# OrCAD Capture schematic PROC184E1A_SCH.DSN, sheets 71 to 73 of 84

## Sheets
71 30. SOC CORE HCPS-B: size C; title: HCPS B; note: PROC184_SCH
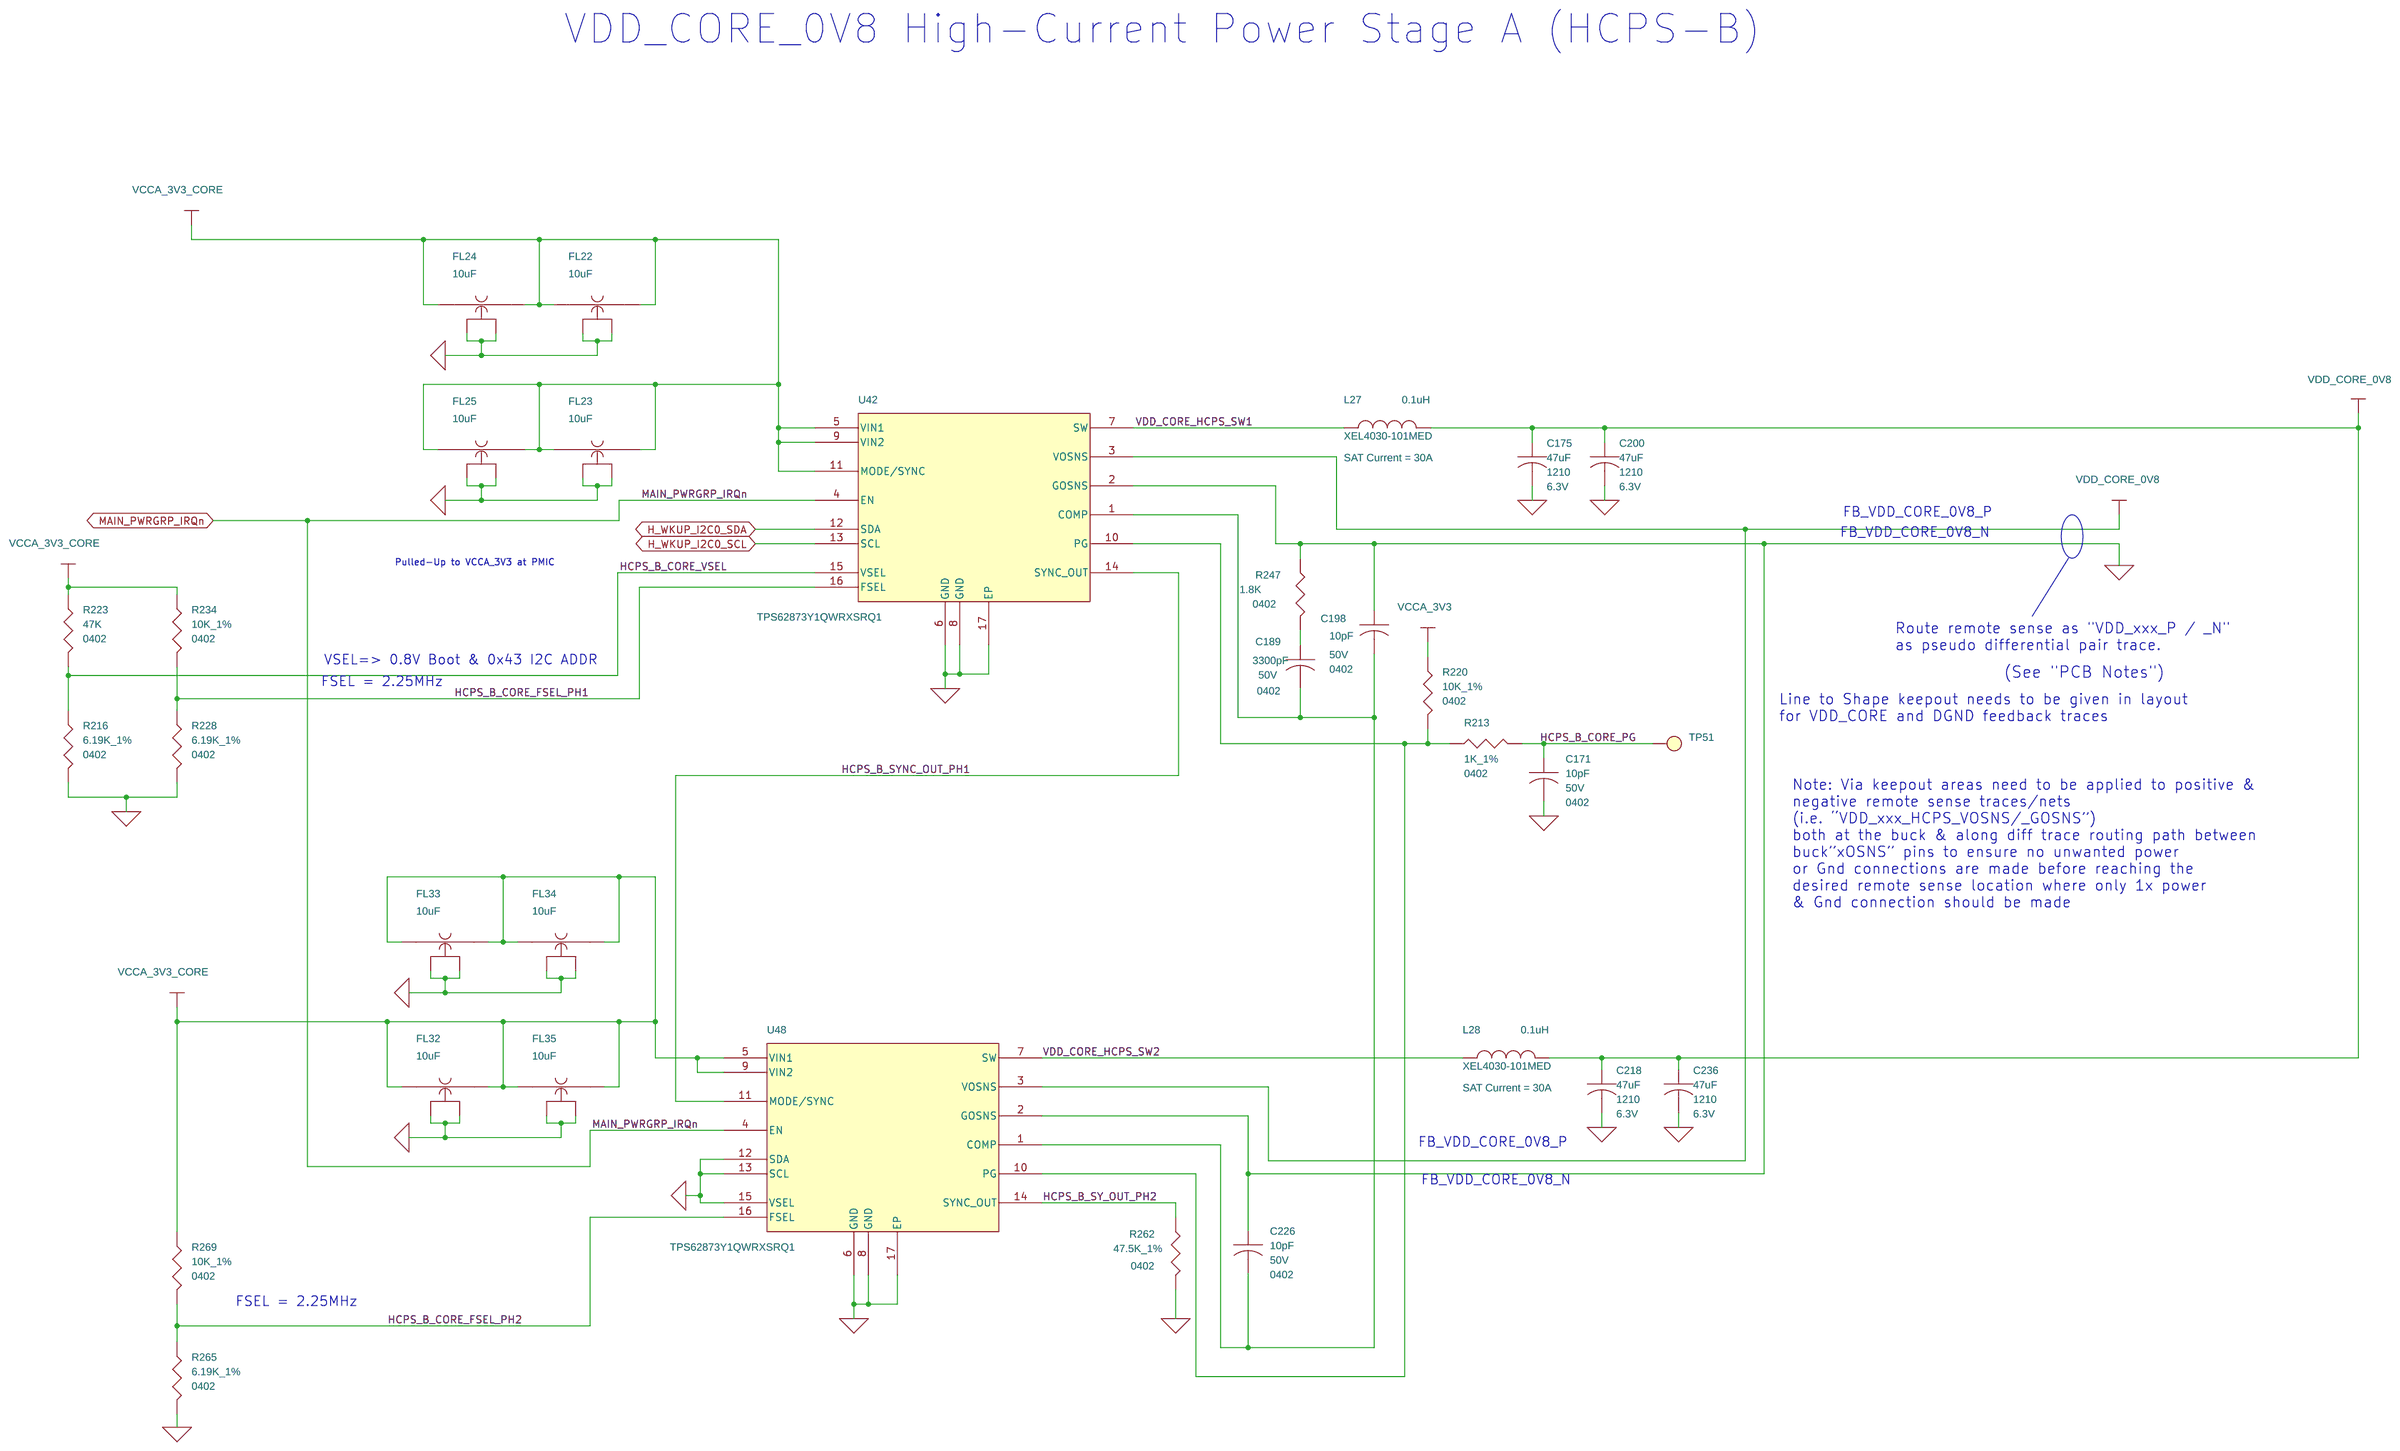
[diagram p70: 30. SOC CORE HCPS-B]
72 31. SOC LDOs & LD SWITCHES: size C; title: SOC LDO's and LD_SWITCHES; note: PROC184_SCH
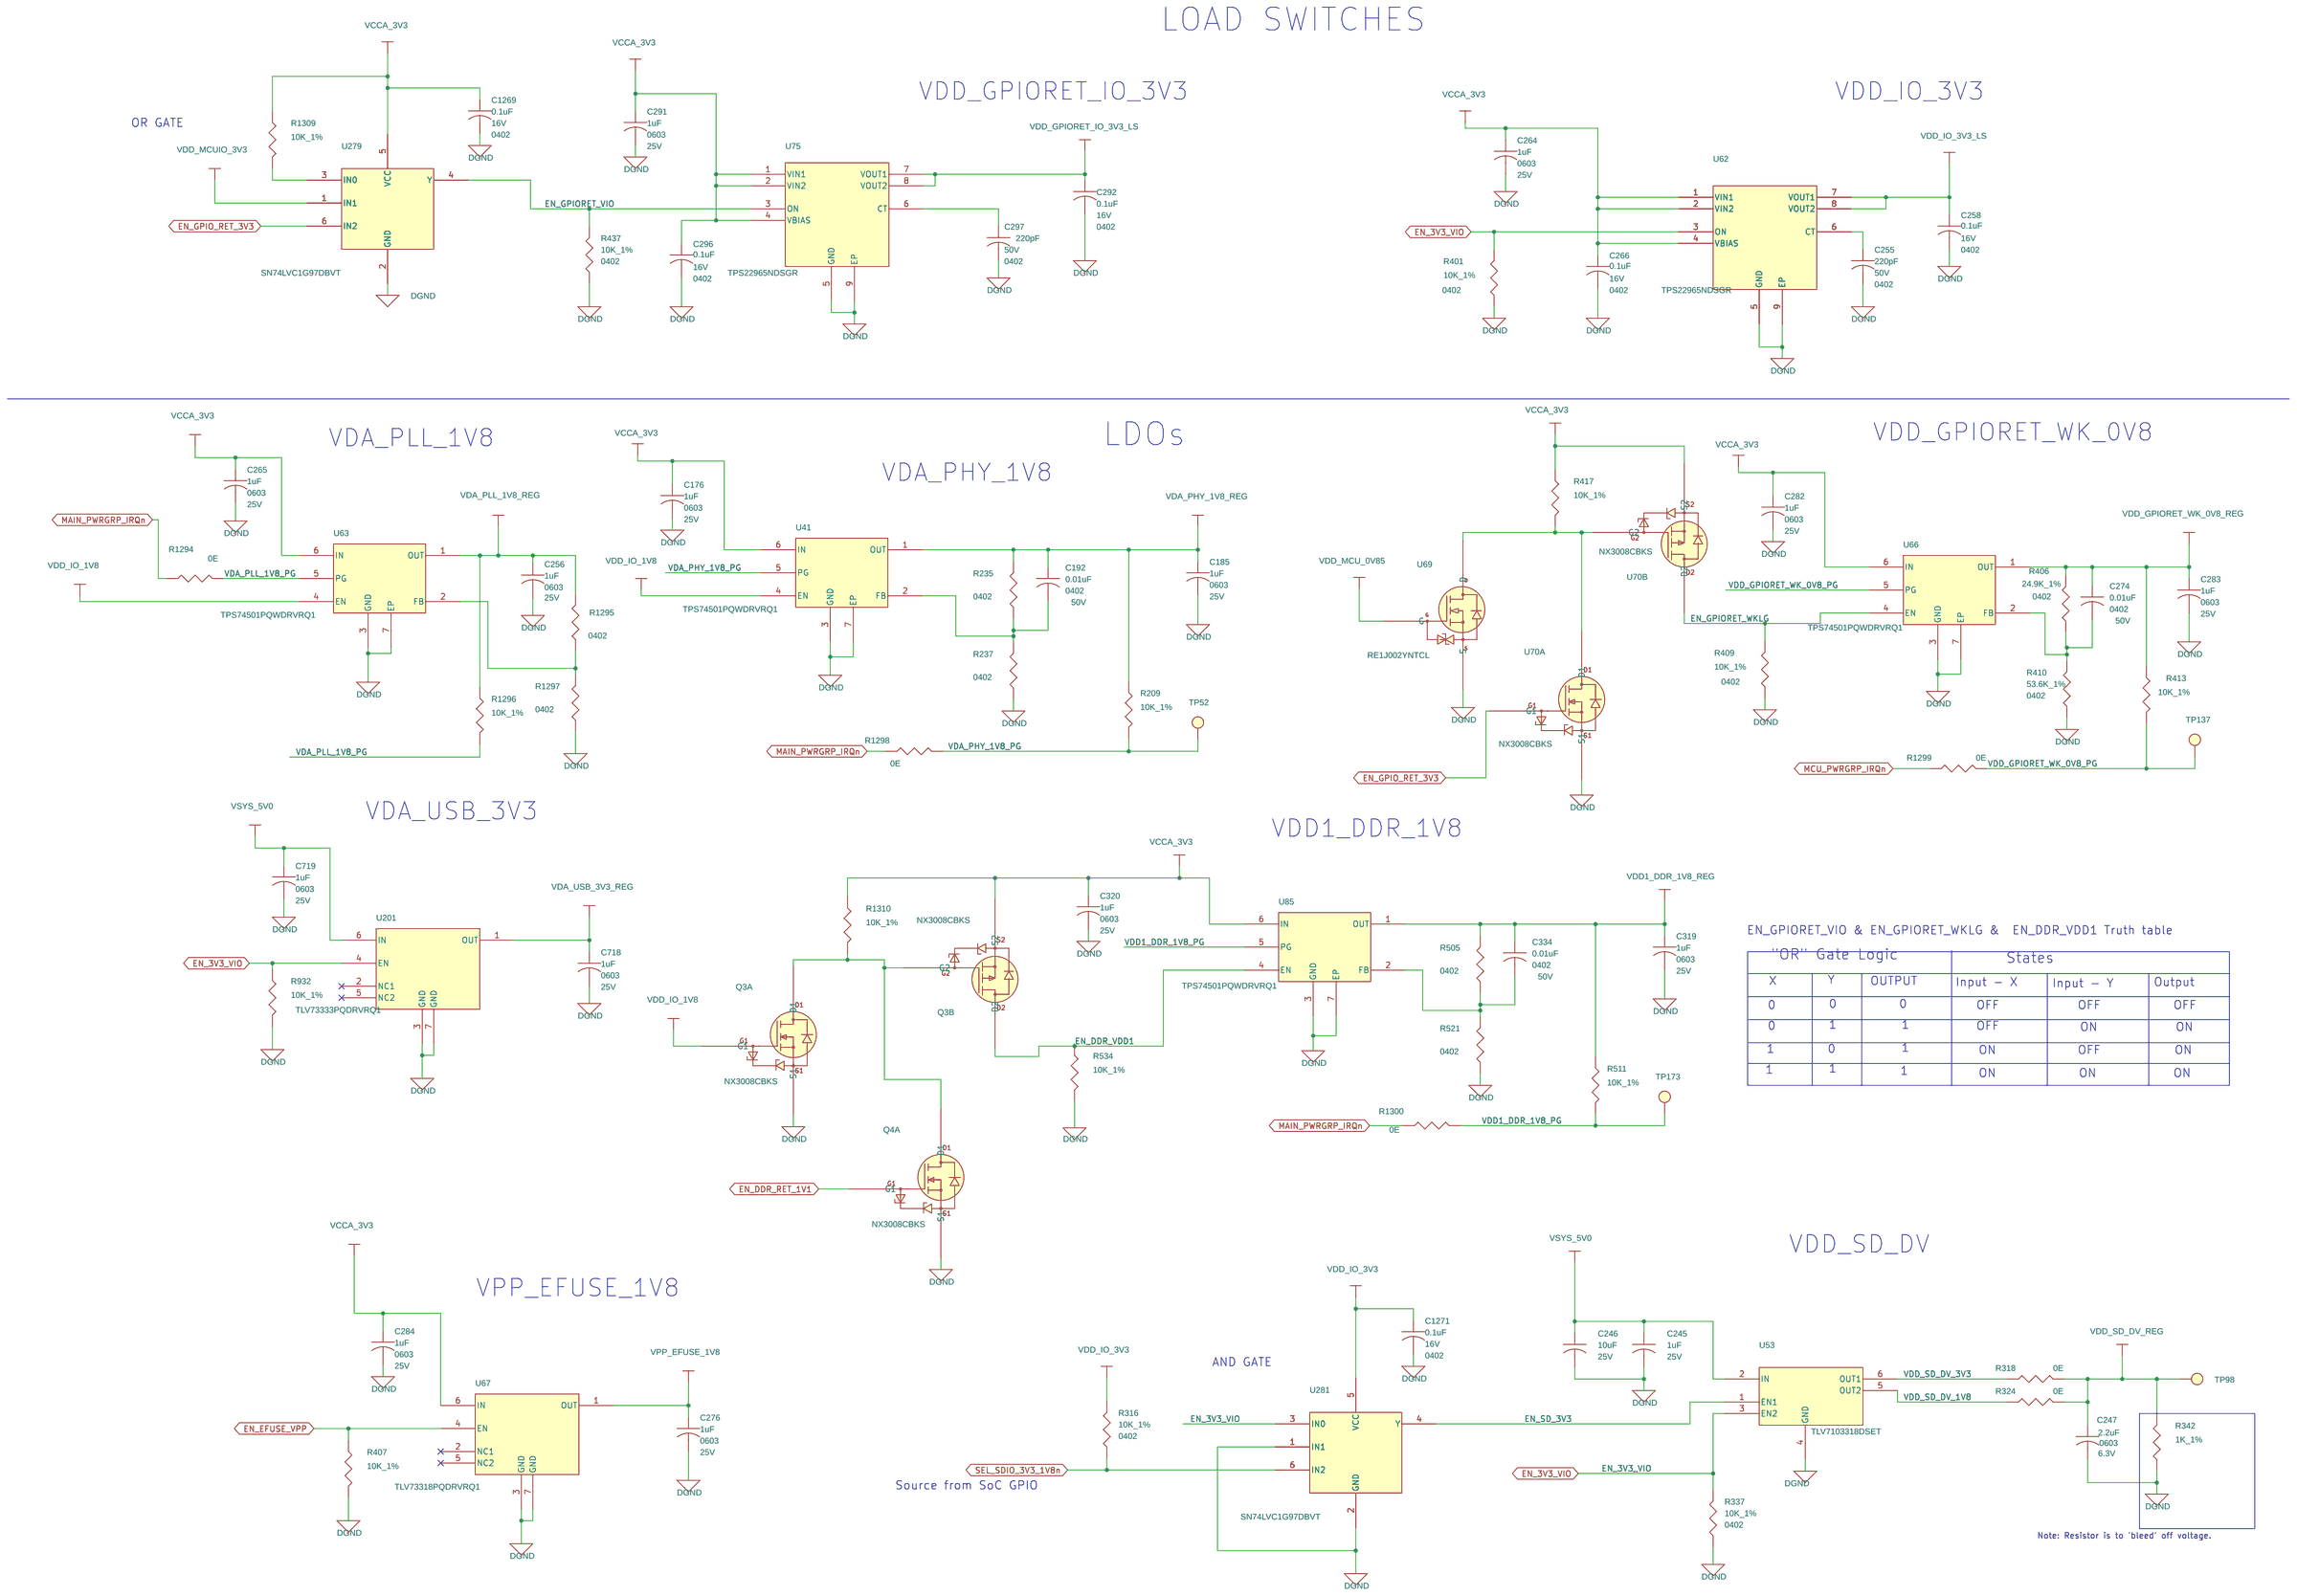
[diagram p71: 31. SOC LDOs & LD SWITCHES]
73 77. EXTERNAL POWER MEASUREMENT: size C; title: EXTERNAL POWER MEASUREMENT WITH ISOLATION; note: PROC184_SCH
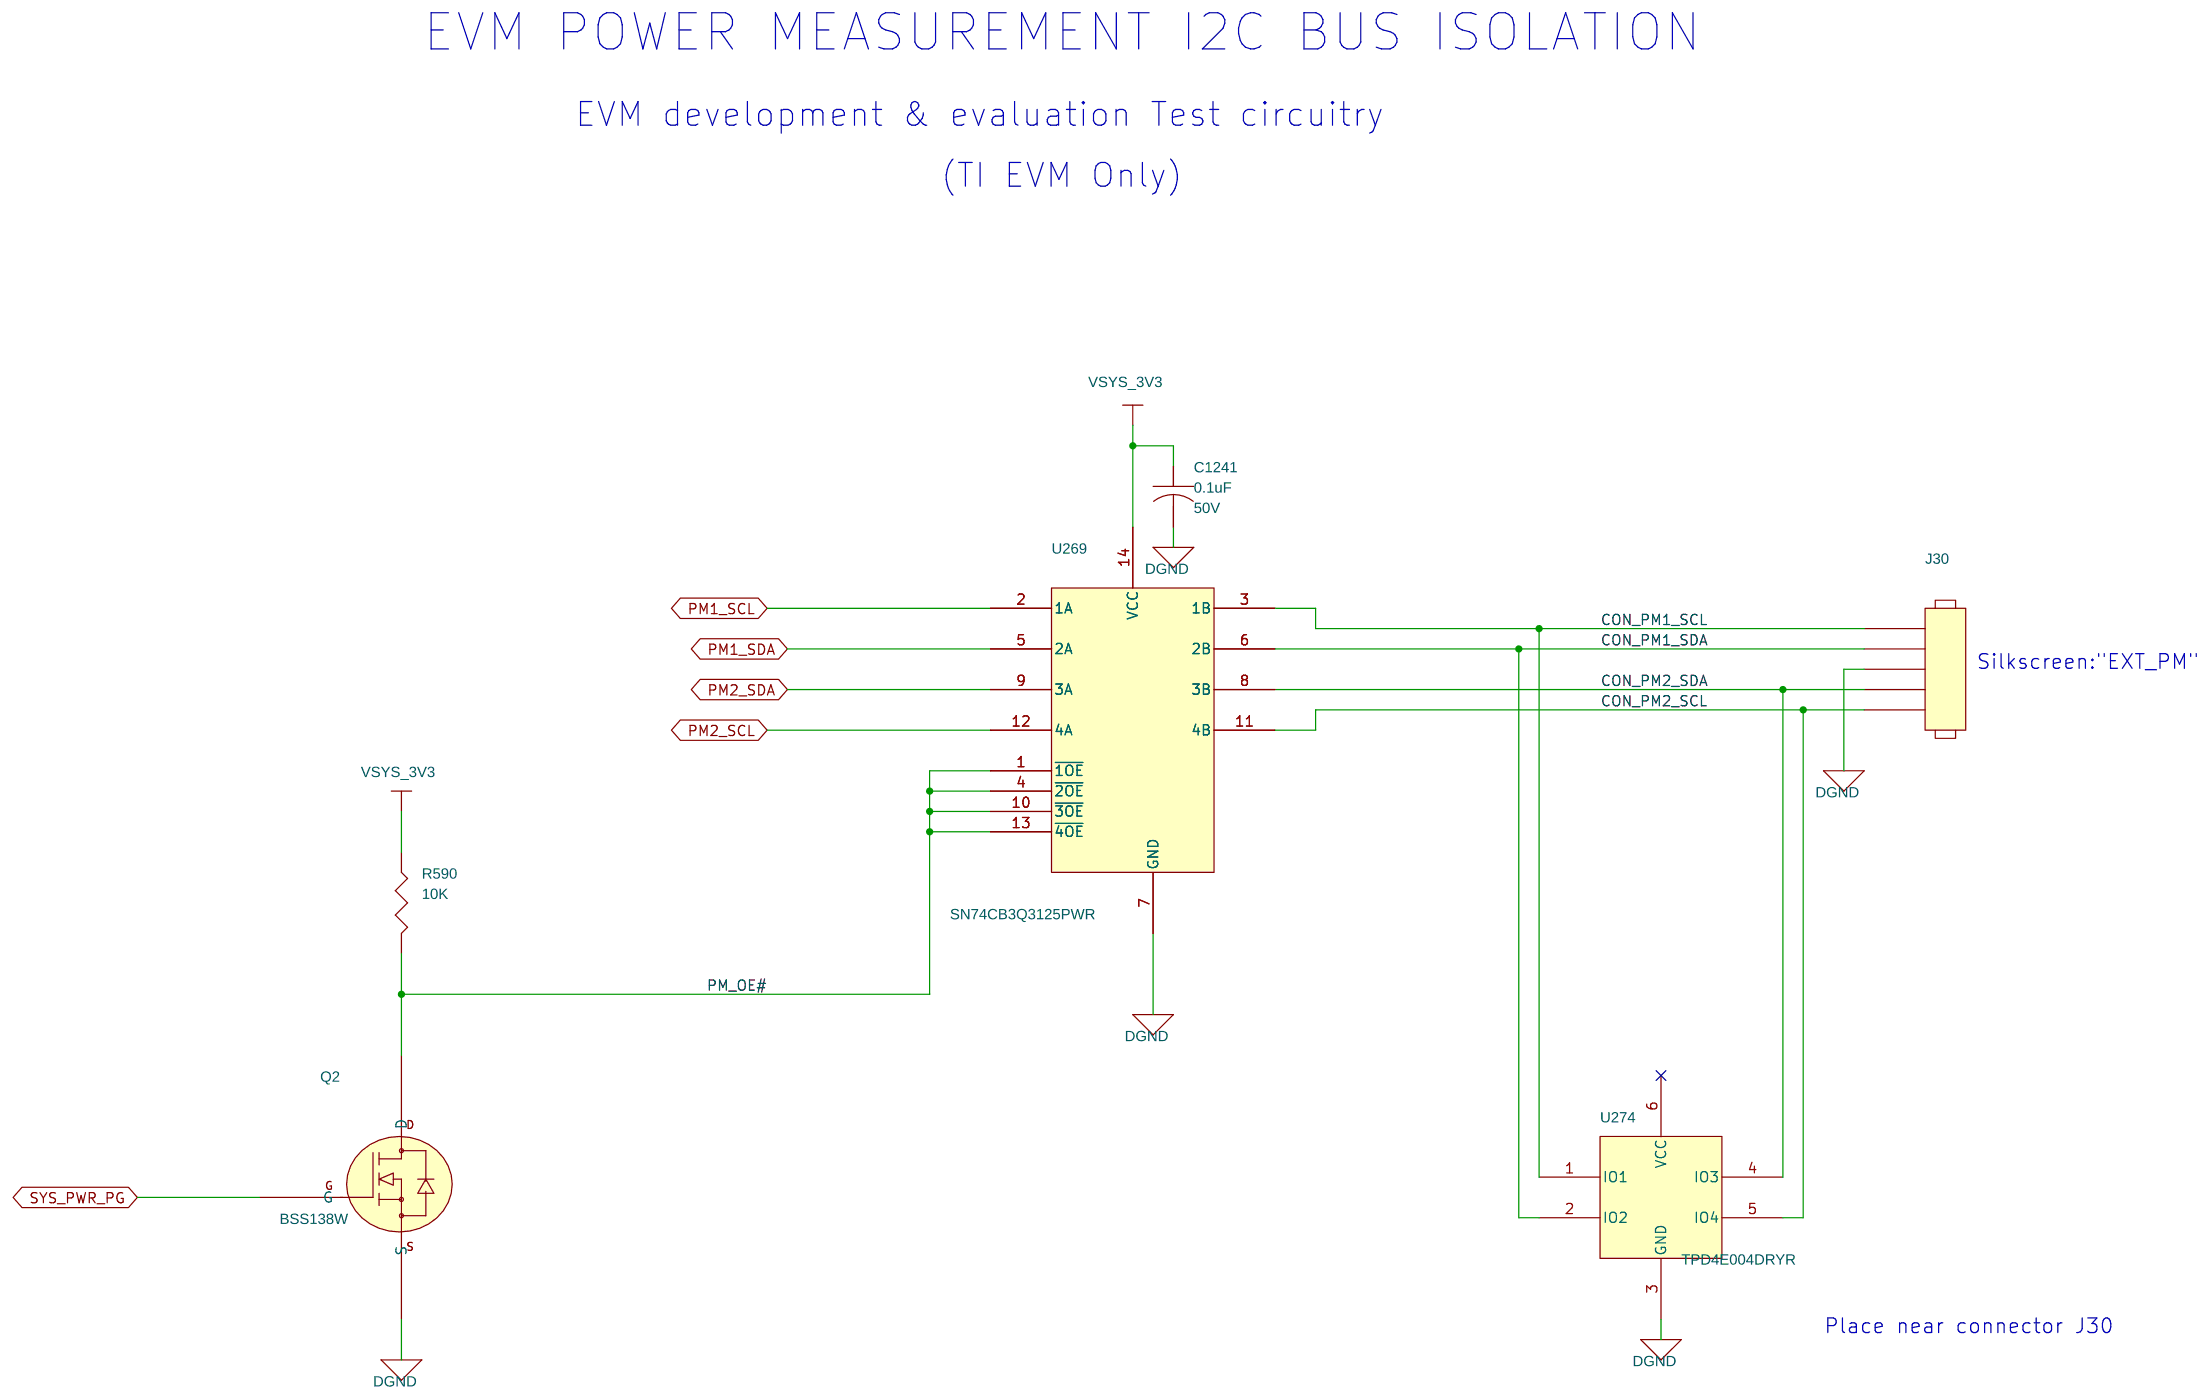
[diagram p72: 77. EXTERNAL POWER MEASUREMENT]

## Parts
sheet 30. SOC CORE HCPS-B
C171  10pF  [CAP0402_0-75]
C175  47uF  [CAP1210_2-75]
C189  3300pF  [CAP0402_0-75]
C198  10pF  [CAP0402_0-75]
C200  47uF  [CAP1210_2-75]
C218  47uF  [CAP1210_2-75]
C226  10pF  [CAP0402_0-75]
C236  47uF  [CAP1210_2-75]
FL22  10uF  [EMIFIL_NFM18C_0603_0-7_TI]
FL23  10uF  [EMIFIL_NFM18C_0603_0-7_TI]
FL24  10uF  [EMIFIL_NFM18C_0603_0-7_TI]
FL25  10uF  [EMIFIL_NFM18C_0603_0-7_TI]
FL32  10uF  [EMIFIL_NFM18C_0603_0-7_TI]
FL33  10uF  [EMIFIL_NFM18C_0603_0-7_TI]
FL34  10uF  [EMIFIL_NFM18C_0603_0-7_TI]
FL35  10uF  [EMIFIL_NFM18C_0603_0-7_TI]
L27  0.1uH  [IND_XEL4030_170X170_SMD_3-2]
L28  0.1uH  [IND_XEL4030_170X170_SMD_3-2]
R213  1K_1%  [RES0402_0-5]
R216  6.19K_1%  [RES0402_0-5]
R220  10K_1%  [RES0402_0-5]
R223  47K  [RES0402_0-5]
R228  6.19K_1%  [RES0402_0-5]
R234  10K_1%  [RES0402_0-5]
R247  1.8K  [RES0402_0-5]
R262  47.5K_1%  [RES0402_0-5]
R265  6.19K_1%  [RES0402_0-5]
R269  10K_1%  [RES0402_0-5]
TP51  TP30_SMD  [TP30_SMD]
U42  TPS62873Y1QWRXSRQ1  [VQFN16_TPS62872-Q1_100X140_1-1]
U48  TPS62873Y1QWRXSRQ1  [VQFN16_TPS62872-Q1_100X140_1-1]
sheet 31. SOC LDOs & LD SWITCHES
C176  1uF  [CAP0603_1]
C185  1uF  [CAP0603_1]
C192  0.01uF  [CAP0402_0-75]
C245  1uF  [CAP0603_1]
C246  10uF  [CAP0603_1-25]
C247  2.2uF  [CAP0603_1]
C255  220pF  [CAP0402_0-75]
C256  1uF  [CAP0603_1]
C258  0.1uF  [CAP0402_0-75]
C264  1uF  [CAP0603_1]
C265  1uF  [CAP0603_1]
C266  0.1uF  [CAP0402_0-75]
C274  0.01uF  [CAP0402_0-75]
C276  1uF  [CAP0603_1]
C282  1uF  [CAP0603_1]
C283  1uF  [CAP0603_1]
C284  1uF  [CAP0603_1]
C291  1uF  [CAP0603_1]
C292  0.1uF  [CAP0402_0-75]
C296  0.1uF  [CAP0402_0-75]
C297  220pF  [CAP0402_0-75]
C319  1uF  [CAP0603_1]
C320  1uF  [CAP0603_1]
C334  0.01uF  [CAP0402_0-75]
C718  1uF  [CAP0603_1]
C719  1uF  [CAP0603_1]
C1269  0.1uF  [CAP0402_0-75]
C1271  0.1uF  [CAP0402_0-75]
Q3  NX3008CBKS  [SOT363-6_1-1]  (sections A,B)
Q4  NX3008CBKS  [SOT363-6_1-1]  (section A)
R209  10K_1%  [RES0402_0-5]
R235  56.2K_1%  [RES0402_0-5]
R237  24.9K_1%  [RES0402_0-5]
R316  10K_1%  [RES0402_0-5]
R318  0E  [RES0402_0-5]
R324  0E  [RES0402_0-5]
R337  10K_1%  [RES0402_0-5]
R342  1K_1%  [RES0402_0-5]
R401  10K_1%  [RES0402_0-5]
R406  24.9K_1%  [RES0402_0-5]
R407  10K_1%  [RES0402_0-5]
R409  10K_1%  [RES0402_0-5]
R410  53.6K_1%  [RES0402_0-5]
R413  10K_1%  [RES0402_0-5]
R417  10K_1%  [RES0402_0-5]
R437  10K_1%  [RES0402_0-5]
R505  56.2K_1%  [RES0402_0-5]
R511  10K_1%  [RES0402_0-5]
R521  24.9K_1%  [RES0402_0-5]
R534  10K_1%  [RES0402_0-5]
R932  10K_1%  [RES0402_0-5]
R1294  0E  [RES0402_0-5]
R1295  56.2K_1%  [RES0402_0-5]
R1296  10K_1%  [RES0402_0-5]
R1297  24.9K_1%  [RES0402_0-5]
R1298  0E  [RES0402_0-5]
R1299  0E  [RES0402_0-5]
R1300  0E  [RES0402_0-5]
R1309  10K_1%  [RES0402_0-5]
R1310  10K_1%  [RES0402_0-5]
TP52  TP30_SMD  [TP30_SMD]
TP98  TP30_SMD  [TP30_SMD]
TP137  TP30_SMD  [TP30_SMD]
TP173  TP30_SMD  [TP30_SMD]
U41  TPS74501PQWDRVRQ1  [SON6_25-59_85X85_0-8]
U53  TLV7103318DSET  [WSON6_19-68_60X60]
U62  TPS22965NDSGR  [WSON8_19-68_80X80_0-8]
U63  TPS74501PQWDRVRQ1  [SON6_25-59_85X85_0-8]
U66  TPS74501PQWDRVRQ1  [SON6_25-59_85X85_0-8]
U67  TLV73318PQDRVRQ1  [SON6_25-59_85X85_0-8]
U69  RE1J002YNTCL  [SOT416F-6_0-9]
U70  NX3008CBKS  [SOT363-6_1-1]  (sections A,B)
U75  TPS22965NDSGR  [WSON8_19-68_80X80_0-8]
U85  TPS74501PQWDRVRQ1  [SON6_25-59_85X85_0-8]
U201  TLV73333PQDRVRQ1  [SON6_25-59_85X85_0-8]
U279  SN74LVC1G97DBVT  [SOT23-6]
U281  SN74LVC1G97DBVT  [SOT23-6]
sheet 77. EXTERNAL POWER MEASUREMENT
C1241  0.1uF  [CAP0402_0-75]
J30  HDR_1X5  [HDR_1X5_68002-205_S_T_8-6]
Q2  BSS138W  [TO_SOT323-123]
R590  10K  [RES0402_0-5]
U269  SN74CB3Q3125PWR  [TSSOP14_25-59_205X180_1-2]
U274  TPD4E004DRYR  [SON6_19-68_40X60_PB_0-6]

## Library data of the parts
C171 C198 C226 = CAP: CAP CERAMIC 10pF 50V 1% C0G(NP0) 0402; Automotive Alternate_mfr_name: TDK; Automotive Alternate_mfr_part_number: CGA2B1X7R1C104K050BC; Chkd/date: VASANTHA/200614; Crtd /date: NAVEED/170614; Custom_Duty: 15%; Customs_HS_Code: 85322990; Direct Alternate_mfr_name: MURATA; Direct Alternate_mfr_part_number: GCM155R71C104JA55D; Distributor_name: DIGIKEY; Distributor_part_number: 478-5717-1-ND; Footprint Path: Y:\MIS_DATABASE\Library\ALTIUM_TOOL\PCB_FOOTPRINTS\Altium_Footprint_Lib.PcbLib; Height: 0.55MM; Library Path: Y:\MIS_DATABASE\Library\ALTIUM_TOOL\SCHEMATICS_PARTS\MS_DISCRETE_Library.schlib; Manufacturer: AVX CORPORATION; Mfr_name: AVX CORPORATION; Mfr_part_number: 04025U100FAT2A; Mistral Part No: 120014060010-R; Package: 0402; Part_type: CAPACITORS\CERAMIC; Project: AEGIS_POM; RoHS: RoHS; Temperature: -55°C+125°C; Tolerance: 1%; Voltage: 50V; Wattage: NA; Weight: 0.65mg; Datasheet: Y:\MIS_DATABASE\DATASHEETS\CAPACITORS\AVX_MLC.PDF
C175 C200 C218 C236 = CAP: CAP CERAMIC 47uF 6.3V 10% X7R AUTO 1210; Automotive Alternate_mfr_name: TDK; Automotive Alternate_mfr_part_number: CGA6P1X7S1A476M; Chkd/date: MANIRAJA/280918; Crtd /date: ALVY/280918; Custom_Duty: 15%; Customs_HS_Code: 85322990; Direct Alternate_mfr_name: TDK; Direct Alternate_mfr_part_number: CGA6P1X7S1A476M; Distributor_name: DIGIKEY; Distributor_part_number: 490-4844-1-ND; Footprint Path: Y:\MIS_DATABASE\Library\ALTIUM_TOOL\PCB_FOOTPRINTS\Altium_Footprint_Lib.PcbLib; Height: 2.70MM; Library Path: Y:\MIS_DATABASE\Library\ALTIUM_TOOL\SCHEMATICS_PARTS\MS_DISCRETE_Library.schlib; Manufacturer: MURATA; Mfr_name: MURATA; Mfr_part_number: GCM32ER70J476KE19L; Mistral Part No: 120018090056-R; Package: 1210; Part_type: CAPACITORS\CERAMIC; Project: TI_J7_SVB-DUT; RoHS: RoHS; Temperature: -55°C+125°C; Tolerance: 10%; Voltage: 6.3V; Wattage: NA; Weight: 110mg; Datasheet: Y:\MIS_DATABASE\DATASHEETS\CAPACITORS\MURATA-GCM-SER.PDF
C189 = CAP: CAP CERAMIC 3300pF 50V 10% X7R 0402; Automotive Alternate_mfr_name: TDK; Automotive Alternate_mfr_part_number: CGA2B1X7R1C104K050BC; Chkd/date: MANIRAJA/180817; Crtd /date: MANIRAJA/180817; Custom_Duty: 15%; Customs_HS_Code: 85322990; Direct Alternate_mfr_name: MURATA; Direct Alternate_mfr_part_number: GCM155R71C104JA55D; Distributor_name: DIGIKEY; Distributor_part_number: 490-3248-1-ND; Footprint Path: Y:\MIS_DATABASE\Library\ALTIUM_TOOL\PCB_FOOTPRINTS\Altium_Footprint_Lib.PcbLib; Height: 0.55MM; Library Path: Y:\MIS_DATABASE\Library\ALTIUM_TOOL\SCHEMATICS_PARTS\MS_DISCRETE_Library.schlib; Manufacturer: MURATA; Mfr_name: MURATA; Mfr_part_number: GRM155R71H332KA01D; Mistral Part No: 120009030367-R; Package: 0402; Part_type: CAPACITORS\CERAMIC; Project: DM8147_PCI CARD; RoHS: RoHS; Temperature: -55°C+125°C; Tolerance: 10%; Voltage: 50V; Wattage: NA; Weight: 6mg; Datasheet: Y:\MIS_DATABASE\DATASHEETS\CAPACITORS\MURATA-GXX-SER_NOV17.PDF
FL22-FL25 FL32-FL35 = CAP_NFM_TI: PASSIVE FILTER EMI 10uF 4V AUTO 0603; Chkd/date: MANIRAJA/251018; Crtd /date: ALVY/251018; Custom_Duty: 15%; Customs_HS_Code: 85412900; Distributor_name: NA; Distributor_part_number: NA; Footprint Path: Y:\MIS_DATABASE\Library\ALTIUM_TOOL\PCB_FOOTPRINTS\Altium_Footprint_Lib.PcbLib; Height: 0.70MM; Library Path: Y:\MIS_DATABASE\Library\ALTIUM_TOOL\SCHEMATICS_PARTS\MS_FILTER_Library.schlib; Mfr_name: MURATA; Mfr_part_number: NFM18HC106D0G_TI; Mistral Part No: 130018100049; Package: 0603; Part_type: FILTER; Project: TI_J7ES_EVM_SOM; RoHS: NA; Temperature: NA; Tolerance: NA; Voltage: 4V; Wattage: NA; Weight: NA; Datasheet: Y:\MIS_DATABASE\DATASHEETS\DISCRETES\INDUCTORS\NFM18HC-SER.PDF
L27 L28 = INDUCTOR: IND POWER 0.1uH 25.8A 20% SMD; Chkd/date: MANIRAJA/170122; Crtd /date: TAMILARASU/170122; Custom_Duty: 24%; Customs_HS_Code: 85437099; Distributor_name: MOUSER; Distributor_part_number: 994-XEL4030-101MED; Footprint Path: Y:\MIS_DATABASE\Library\ALTIUM_TOOL\PCB_FOOTPRINTS\Altium_Footprint_Lib.PcbLib; Height: 3.20MM; Library Path: Y:\MIS_DATABASE\Library\ALTIUM_TOOL\SCHEMATICS_PARTS\MS_DISCRETE_Library.schlib; Manufacturer: COILCRAFT; Mfr_name: COILCRAFT; Mfr_part_number: XEL4030-101MED; Mistral Part No: 130022010018-R; Package: SMD; Part #: 105324-1470R; Project: J7AHP_PROTO_BRD; RoHS: RoHS; SAT Current: 30A; Temperature: -40°C+125°C; Tolerance: 20%; Voltage: NA; Wattage: NA; Weight: 280mg; Datasheet: Y:\MIS_DATABASE\DATASHEETS\DISCRETES\INDUCTORS\XEL4030_JUN20.PDF
R213 R342 = RESISTOR: RES 1K 1/10W 1% 0402; Chkd/date: VASANTHA/281216; Crtd /date: MAZHAR/150506; Custom_Duty: 15%; Customs_HS_Code: 85332119; Distributor_name: DIGIKEY; Distributor_part_number: P1.00KLCT-ND; Footprint Path: Y:\MIS_DATABASE\Library\ALTIUM_TOOL\PCB_FOOTPRINTS\Altium_Footprint_Lib.PcbLib; Height: 0.40MM; Library Path: Y:\MIS_DATABASE\Library\ALTIUM_TOOL\SCHEMATICS_PARTS\MS_DISCRETE_Library.schlib; Manufacturer: PANASONIC-ECG; Mfr_name: PANASONIC-ECG; Mfr_part_number: ERJ-2RKF1001X; Mistral Part No: 110009030411-R; Package: 0402; Part_type: RESISTORS\FIXED; Project: VOCERA; RoHS: RoHS; Temperature: -55°C+155°C; Tolerance: 1%; Voltage: NA; Wattage: 1/10W; Weight: 0.8mg; Datasheet: Y:\MIS_DATABASE\DATASHEETS\RESISTORS\PAN-ERJSER_NOV17.PDF
R216 R228 R265 = RESISTOR: RES 6.19K 1/16W 1% 0402; Chkd/date: MANIRAJA/190122; Crtd /date: TAMILARASU/190122; Custom_Duty: 15%; Customs_HS_Code: 85332119; Distributor_name: DIGIKEY; Distributor_part_number: 311-6.19KLRCT-ND; Footprint Path: Y:\MIS_DATABASE\Library\ALTIUM_TOOL\PCB_FOOTPRINTS\Altium_Footprint_Lib.PcbLib; Height: 0.40MM; Library Path: Y:\MIS_DATABASE\Library\ALTIUM_TOOL\SCHEMATICS_PARTS\MS_DISCRETE_Library.schlib; Manufacturer: YAGEO AMERICA; Mfr_name: YAGEO AMERICA; Mfr_part_number: RC0402FR-076K19L; Mistral Part No: 110022010013-R; Package: 0402; Part_type: RESISTORS\FIXED; Project: J7AHP_PROTO_BRD; RoHS: RoHS; Temperature: -55°C+155°C; Tolerance: 1%; Voltage: NA; Wattage: 1/16W; Weight: 0.65mg; Datasheet: Y:\MIS_DATABASE\DATASHEETS\RESISTORS\RCXXXXL-SER_MAR18.PDF
R220 R234 R269 R316 R337 R407 R417 R437 R534 R932 R1309 R1310 = RESISTOR: RES 10K 1/16W 1% 0402; Chkd/date: VASANTHA/201216; Crtd /date: GEETHA/290506; Custom_Duty: 15%; Customs_HS_Code: 85332119; Distributor_name: DIGIKEY; Distributor_part_number: 311-10.0KLRTR-ND; Footprint Path: Y:\MIS_DATABASE\Library\ALTIUM_TOOL\PCB_FOOTPRINTS\Altium_Footprint_Lib.PcbLib; Height: 0.40MM; Library Path: Y:\MIS_DATABASE\Library\ALTIUM_TOOL\SCHEMATICS_PARTS\MS_DISCRETE_Library.schlib; Manufacturer: YAGEO AMERICA; Mfr_name: YAGEO AMERICA; Mfr_part_number: RC0402FR-0710KL; Mistral Part No: 110015090015-R; Package: 0402; Part_type: RESISTORS\FIXED; Project: VOCERA; RoHS: RoHS; Temperature: -55°C+155°C; Tolerance: 1%; Voltage: NA; Wattage: 1/16W; Weight: 0.65mg; Datasheet: Y:\MIS_DATABASE\DATASHEETS\RESISTORS\RCXXXXL-SER_MAR18.PDF
R223 = RESISTOR: RES 47K 1/10W 5% 0402; Chkd/date: VASANTHA/281216; Crtd /date: MAZHAR/120505; Custom_Duty: 15%; Customs_HS_Code: 85332119; Distributor_name: DIGIKEY; Distributor_part_number: P47KJCT-ND; Footprint Path: Y:\MIS_DATABASE\Library\ALTIUM_TOOL\PCB_FOOTPRINTS\Altium_Footprint_Lib.PcbLib; Height: 0.40MM; Library Path: Y:\MIS_DATABASE\Library\ALTIUM_TOOL\SCHEMATICS_PARTS\MS_DISCRETE_Library.schlib; Manufacturer: PANASONIC-ECG; Mfr_name: PANASONIC-ECG; Mfr_part_number: ERJ-2GEJ473X; Mistral Part No: 110009030882-R; Package: 0402; Part_type: RESISTORS\FIXED; Project: CTP02_REVA_BASE; RoHS: RoHS; Temperature: -55°C+155°C; Tolerance: 5%; Voltage: NA; Wattage: 1/10W; Weight: 0.8mg; Datasheet: Y:\MIS_DATABASE\DATASHEETS\RESISTORS\PAN-ERJSER_NOV17.PDF
R247 = RESISTOR: RES 1.8K 1/16W 5% AUTO 0402; Chkd/date: MAZHAR/170709; Crtd /date: MAZHAR/200907; Custom_Duty: 15%; Customs_HS_Code: 85332119; Distributor_name: DIGIKEY; Distributor_part_number: RHM1.8KJCT-ND; Footprint Path: Y:\MIS_DATABASE\Library\ALTIUM_TOOL\PCB_FOOTPRINTS\Altium_Footprint_Lib.PcbLib; Height: 0.40MM; Library Path: Y:\MIS_DATABASE\Library\ALTIUM_TOOL\SCHEMATICS_PARTS\MS_DISCRETE_Library.schlib; Manufacturer: ROHM; Mfr_name: ROHM; Mfr_part_number: MCR01MZPJ182; Mistral Part No: 110009030147-R; Package: 0402; Part_type: RESISTORS\FIXED; Project: MARP; RoHS: RoHS; Temperature: -55°C+155°C; Tolerance: 5%; Voltage: NA; Wattage: 1/16W; Weight: 0.57mg; Datasheet: Y:\MIS_DATABASE\DATASHEETS\RESISTORS\MCR10.PDF
R262 = RESISTOR: RES 47.5K 1/16W 1% 0402; Chkd/date: MANIRAJA/170320; Crtd /date: MANIRAJA/170320; Custom_Duty: 15%; Customs_HS_Code: 85332119; Distributor_name: DIGIKEY; Distributor_part_number: 541-47.5KLCT-ND; Footprint Path: Y:\MIS_DATABASE\Library\ALTIUM_TOOL\PCB_FOOTPRINTS\Altium_Footprint_Lib.PcbLib; Height: 0.40MM; Library Path: Y:\MIS_DATABASE\Library\ALTIUM_TOOL\SCHEMATICS_PARTS\MS_DISCRETE_Library.schlib; Manufacturer: VISHAY; Mfr_name: VISHAY; Mfr_part_number: CRCW040247K5FKED; Mistral Part No: 110017010006-R; Package: 0402; Part_type: RESISTORS\FIXED; Project: TPR12_SVB; RoHS: RoHS; Temperature: -55°C+155°C; Tolerance: 1%; Voltage: NA; Wattage: 1/16W; Weight: 0.65mg; Datasheet: Y:\MIS_DATABASE\DATASHEETS\RESISTORS\CRCW0603.PDF
TP51 TP98 = TESTPOINT: TESTPOINT CIR 30 SMD; Chkd/date: SHREESHAIL/171006; Crtd /date: MAZHAR/171006; Custom_Duty: NA; Customs_HS_Code: NA; Distributor_name: NA; Distributor_part_number: NA; Footprint Path: Y:\MIS_DATABASE\Library\ALTIUM_TOOL\PCB_FOOTPRINTS\Altium_Footprint_Lib.PcbLib; Height: NA; Library Path: Y:\MIS_DATABASE\Library\ALTIUM_TOOL\SCHEMATICS_PARTS\MS_DISCRETE_Library.schlib; MECHANICAL 3D STEP FILE: NA; Manufacturer: LOCAL; Mfr_name: LOCAL; Mistral Part No: 130009030930; Package: SMD; Project: BT MODULE_CSRBC04; RoHS: NA; Temperature: NA; Tolerance: NA; Voltage: NA; Wattage: NA; Weight: NA; Datasheet: NA
U42 U48 = TPS62872-Q1_VQFN16: IC 2.7-6V INPUT 15A STACKABLE FAST TRANSIENT SYNCHRONOUS STEP-DOWN DC-DC CONVERTER VQFN16; Chkd/date: ALVY/280322; Crtd /date: ALVY/280322; Custom_Duty: 15%; Customs_HS_Code: 85423100; Distributor_name: NA; Distributor_part_number: NA; Footprint Path: Y:\MIS_DATABASE\Library\ALTIUM_TOOL\PCB_FOOTPRINTS\Altium_Footprint_Lib.PcbLib; Height: 1.05MM; Library Path: Y:\MIS_DATABASE\Library\ALTIUM_TOOL\SCHEMATICS_PARTS\MS_MISCPOWER_Library.schlib; Manufacturer: TEXAS INSTRUMENTS; Mfr_name: TEXAS INSTRUMENTS; Mistral Part No: 142022030022; Package: VQFN16; Part_type: ICS\POWER\DC-DC CONVERTER; Project: TI_J7AHP_EVM_BRD; Remarks: CREATED SAME AS  TPS62873QWRXSR-Q1; RoHS: NA; Temperature: -40°C+150°C; Tolerance: NA; Voltage: NA; Wattage: NA; Weight: NA; Datasheet: Y:\MIS_DATABASE\DATASHEETS\ICS\POWER\TPS6287X-Q1.PDF
C176 C185 C256 C264 C265 C276 C282-C284 C291 C319 C320 C718 C719 = CAP: CAP CERAMIC 1uF 25V 10% X7R 0603; Automotive Alternate_mfr_name: TDK; Automotive Alternate_mfr_part_number: CGA3E1X7R1E105K080AC; Chkd/date: MANIRAJA/070319; Crtd /date: ALVY/070319; Custom_Duty: 15%; Customs_HS_Code: 85322990; Direct Alternate_mfr_name: SAMSUNG; Direct Alternate_mfr_part_number: CL10B105KA8NNNC; Distributor_name: DIGIKEY; Distributor_part_number: 445-173615-1-ND; Footprint Path: Y:\MIS_DATABASE\Library\ALTIUM_TOOL\PCB_FOOTPRINTS\Altium_Footprint_Lib.PcbLib; Height: 0.95MM; Library Path: Y:\MIS_DATABASE\Library\ALTIUM_TOOL\SCHEMATICS_PARTS\MS_DISCRETE_Library.schlib; Manufacturer: TDK CORPORATION; Mfr_name: TDK CORPORATION; Mfr_part_number: C1608X7R1E105K080AE; Mistral Part No: 120011010017-R; Package: 0603; Part #: 104865-0100R; Part_type: CAPACITORS\CERAMIC; Project: TI_J7ES_EVM_SOM; RoHS: RoHS; Temperature: -55°C+125°C; Tolerance: 10%; Voltage: 25V; Wattage: NA; Weight: 2mg; Datasheet: Y:\MIS_DATABASE\DATASHEETS\CAPACITORS\TDK-CAP-E-SER.PDF
C192 C274 C334 = CAP: CAP CERAMIC 0.01uF 50V 10% X7R 0402; Automotive Alternate_mfr_name: TDK; Automotive Alternate_mfr_part_number: CGA2B3X7R1H103K050BB; Chkd/date: MANIRAJA/280319; Crtd /date: MANIRAJA/280319; Custom_Duty: 15%; Customs_HS_Code: 85322990; Direct Alternate_mfr_name: TDK; Direct Alternate_mfr_part_number: C1005X7R1H103K050BE; Distributor_name: DIGIKEY; Distributor_part_number: 490-4516-1-ND; Footprint Path: Y:\MIS_DATABASE\Library\ALTIUM_TOOL\PCB_FOOTPRINTS\Altium_Footprint_Lib.PcbLib; Height: 0.55MM; Library Path: Y:\MIS_DATABASE\Library\ALTIUM_TOOL\SCHEMATICS_PARTS\MS_DISCRETE_Library.schlib; Manufacturer: MURATA; Mfr_name: MURATA; Mfr_part_number: GRM155R71H103KA88D; Mistral Part No: 120009030025-R; Package: 0402; Part #: 104725-1101R; Part_type: CAPACITORS\CERAMIC; Project: G4_SVGA; RoHS: RoHS; Temperature: -55°C+125°C; Tolerance: 10%; Voltage: 50V; Wattage: NA; Weight: 0.65mg; Datasheet: Y:\MIS_DATABASE\DATASHEETS\CAPACITORS\GRM155R71H103KA88D.PDF
C245 = CAP: CAP CERAMIC 1uF 25V 10% X7R 0603; Automotive Alternate_mfr_name: TDK; Automotive Alternate_mfr_part_number: CGA3E1X7R1E105K080AC; Chkd/date: MANIRAJA/070319; Crtd /date: ALVY/070319; Custom_Duty: 15%; Customs_HS_Code: 85322990; Direct Alternate_mfr_name: SAMSUNG; Direct Alternate_mfr_part_number: CL10B105KA8NNNC; Distributor_name: DIGIKEY; Distributor_part_number: 445-173615-1-ND; Footprint Path: Y:\MIS_DATABASE\Library\ALTIUM_TOOL\PCB_FOOTPRINTS\Altium_Footprint_Lib.PcbLib; Height: 0.95MM; Library Path: Y:\MIS_DATABASE\Library\ALTIUM_TOOL\SCHEMATICS_PARTS\MS_DISCRETE_Library.schlib; Manufacturer: TDK CORPORATION; Mfr_name: TDK CORPORATION; Mfr_part_number: C1608X7R1E105K080AE; Mistral Part No: 120011010017-R; Package: 0603; Part_type: CAPACITORS\CERAMIC; Project: TI_J7ES_EVM_SOM; RoHS: RoHS; Temperature: -55°C+125°C; Tolerance: 10%; Voltage: 25V; Wattage: NA; Weight: 2mg; Datasheet: Y:\MIS_DATABASE\DATASHEETS\CAPACITORS\TDK-CAP-E-SER.PDF
C246 = CAP: CAP CERAMIC 10uF 25V 20% X5R 0603; Chkd/date: MANIRAJA/040718; Crtd /date: MANIRAJA/040718; Custom_Duty: 15%; Customs_HS_Code: 85322990; Direct Alternate_mfr_name: SAMSUNG; Direct Alternate_mfr_part_number: CL10X106MO8NRNC; Distributor_name: DIGIKEY; Distributor_part_number: 490-10991-1-ND; Footprint Path: Y:\MIS_DATABASE\Library\ALTIUM_TOOL\PCB_FOOTPRINTS\Altium_Footprint_Lib.PcbLib; Height: 1.20MM; Library Path: Y:\MIS_DATABASE\Library\ALTIUM_TOOL\SCHEMATICS_PARTS\MS_DISCRETE_Library.schlib; Manufacturer: MURATA; Mfr_name: MURATA; Mfr_part_number: ZRB18AR61E106ME01L; Mistral Part No: 120018070001-R; Package: 0603; Part_type: CAPACITORS\CERAMIC; Project: CABS_VME_DIO; RoHS: RoHS; Temperature: -55°C+85°C; Tolerance: 20%; Voltage: 25V; Wattage: NA; Weight: 2mg; Datasheet: Y:\MIS_DATABASE\DATASHEETS\CAPACITORS\ZRB18AR61E106ME01L.PDF
C247 = CAP: CAP CERAMIC 2.2uF 6.3V 10% X7R AUTO 0603; Automotive Alternate_mfr_name: TDK; Automotive Alternate_mfr_part_number: CGA3E1X7R0J225K080AC; Chkd/date: MANIRAJA/050419; Crtd /date: ALVY/050419; Custom_Duty: 15%; Customs_HS_Code: 85322990; Direct Alternate_mfr_name: TDK; Direct Alternate_mfr_part_number: CGA3E1X7R0J225K080AC; Distributor_name: DIGIKEY; Distributor_part_number: 490-5316-1-ND; Footprint Path: Y:\MIS_DATABASE\Library\ALTIUM_TOOL\PCB_FOOTPRINTS\Altium_Footprint_Lib.PcbLib; Height: 0.90MM; Library Path: Y:\MIS_DATABASE\Library\ALTIUM_TOOL\SCHEMATICS_PARTS\MS_DISCRETE_Library.schlib; Manufacturer: MURATA; Mfr_name: MURATA; Mfr_part_number: GCM188R70J225KE22D; Mistral Part No: 120019040009-R; Package: 0603; Part_type: CAPACITORS\CERAMIC; Project: J7ES_SOM_DUAL-LEO_PMIC; RoHS: RoHS; Temperature: -55°C+125°C; Tolerance: 10%; Voltage: 6.3V; Wattage: NA; Weight: 6.3mg; Datasheet: Y:\MIS_DATABASE\DATASHEETS\CAPACITORS\GCM188R70J225KE22.PDF
C255 C297 = CAP: CAP CERAMIC 220pF 50V 2% C0G(NP0) 0402; Chkd/date: MANIRAJA/030619; Crtd /date: ALVY/310519; Custom_Duty: 15%; Customs_HS_Code: 85322990; Distributor_name: DIGIKEY; Distributor_part_number: 311-3739-1-ND; Footprint Path: Y:\MIS_DATABASE\Library\ALTIUM_TOOL\PCB_FOOTPRINTS\Altium_Footprint_Lib.PcbLib; Height: 0.55MM; Library Path: Y:\MIS_DATABASE\Library\ALTIUM_TOOL\SCHEMATICS_PARTS\MS_DISCRETE_Library.schlib; Manufacturer: YAGEO AMERICA; Mfr_name: YAGEO AMERICA; Mfr_part_number: CC0402GRNPO9BN221; Mistral Part No: 120014070004-R; Package: 0402; Part #: 101782-1223R; Part_type: CAPACITORS\CERAMIC; Project: J7ES_SOM_DUAL-LEO_PMIC; RoHS: RoHS; Temperature: -55°C+125°C; Tolerance: 2%; Voltage: 50V; Wattage: NA; Weight: 0.65mg; Datasheet: Y:\MIS_DATABASE\DATASHEETS\CAPACITORS\YACC-NPO.PDF
C258 C266 C292 C296 = CAP: CAP CERAMIC 0.1uF 16V 10% X7R AUTO 0402; Automotive Alternate_mfr_name: TDK; Automotive Alternate_mfr_part_number: CGA2B1X7R1C104K050BC; Chkd/date: NAVEED/021014; Crtd /date: VASANTHA/300514; Custom_Duty: 15%; Customs_HS_Code: 85322990; Direct Alternate_mfr_name: MURATA; Direct Alternate_mfr_part_number: GCM155R71C104JA55D; Distributor_name: DIGIKEY; Distributor_part_number: 490-4759-1-ND; Footprint Path: Y:\MIS_DATABASE\Library\ALTIUM_TOOL\PCB_FOOTPRINTS\Altium_Footprint_Lib.PcbLib; Height: 0.55MM; Library Path: Y:\MIS_DATABASE\Library\ALTIUM_TOOL\SCHEMATICS_PARTS\MS_DISCRETE_Library.schlib; Manufacturer: MURATA; Mfr_name: MURATA; Mfr_part_number: GCM155R71C104KA55D; Mistral Part No: 120016070006-R; Package: 0402; Part #: 104446-1100R; Part_type: CAPACITORS\CERAMIC; Project: DCMIST_FPGA_CARD; RoHS: RoHS; Temperature: -55°C+125°C; Tolerance: 10%; Voltage: 16V; Wattage: NA; Weight: 6mg; Datasheet: Y:\MIS_DATABASE\DATASHEETS\CAPACITORS\MURATA-GCM-SER.PDF
C1269 C1271 = CAP: CAP CERAMIC 0.1uF 16V 10% X7R AUTO 0402; Automotive Alternate_mfr_name: TDK; Automotive Alternate_mfr_part_number: CGA2B1X7R1C104K050BC; Chkd/date: NAVEED/021014; Crtd /date: VASANTHA/300514; Custom_Duty: 15%; Customs_HS_Code: 85322990; Direct Alternate_mfr_name: MURATA; Direct Alternate_mfr_part_number: GCM155R71C104JA55D; Distributor_name: DIGIKEY; Distributor_part_number: 490-4759-1-ND; Footprint Path: Y:\MIS_DATABASE\Library\ALTIUM_TOOL\PCB_FOOTPRINTS\Altium_Footprint_Lib.PcbLib; Height: 0.55MM; Library Path: Y:\MIS_DATABASE\Library\ALTIUM_TOOL\SCHEMATICS_PARTS\MS_DISCRETE_Library.schlib; Manufacturer: MURATA; Mfr_name: MURATA; Mfr_part_number: GCM155R71C104KA55D; Mistral Part No: 120016070006-R; Package: 0402; Part_type: CAPACITORS\CERAMIC; Project: DCMIST_FPGA_CARD; RoHS: RoHS; Temperature: -55°C+125°C; Tolerance: 10%; Voltage: 16V; Wattage: NA; Weight: 6mg; Datasheet: Y:\MIS_DATABASE\DATASHEETS\CAPACITORS\MURATA-GCM-SER.PDF
Q3 Q4 = MOSFET_NX3008CBKS: TRANSISTOR MOSFET N/P CHANNEL TRENCH 30V 350/200mA SC88-6; Chkd/date: MANIRAJA/311018; Crtd /date: ALVY/311018; Custom_Duty: 15%; Customs_HS_Code: 85412900; Distributor_name: DIGIKEY; Distributor_part_number: 1727-1278-1-ND; Footprint Path: Y:\MIS_DATABASE\Library\ALTIUM_TOOL\PCB_FOOTPRINTS\Altium_Footprint_Lib.PcbLib; Height: 1.10MM; Library Path: Y:\MIS_DATABASE\Library\ALTIUM_TOOL\SCHEMATICS_PARTS\MS_MOSFET_Library.schlib; Mfr_name: NEXPERIA; Mfr_part_number: NX3008CBKS,115; Mistral Part No: 130018100059-R; Package: SC88-6; Part_type: TRANSISTOR\MOSFET; Project: TI_J7ES_EVM_SOM; RoHS: RoHS; Temperature: -55°C+150°C; Tolerance: NA; Voltage: NA; Wattage: NA; Weight: 7.51mg; Datasheet: Y:\MIS_DATABASE\DATASHEETS\DISCRETES\TRANSISTORS_FETS\NX3008CBKS.PDF
R209 R401 R409 R413 R511 R1296 = RESISTOR: RES 10K 1/16W 1% 0402; Chkd/date: VASANTHA/201216; Crtd /date: GEETHA/290506; Custom_Duty: 15%; Customs_HS_Code: 85332119; Distributor_name: DIGIKEY; Distributor_part_number: 311-10.0KLRTR-ND; Footprint Path: Y:\MIS_DATABASE\Library\ALTIUM_TOOL\PCB_FOOTPRINTS\Altium_Footprint_Lib.PcbLib; Height: 0.40MM; Library Path: Y:\MIS_DATABASE\Library\ALTIUM_TOOL\SCHEMATICS_PARTS\MS_DISCRETE_Library.schlib; Manufacturer: YAGEO AMERICA; Mfr_name: YAGEO AMERICA; Mfr_part_number: RC0402FR-0710KL; Mistral Part No: 110015090015-R; Package: 0402; Part #: 102145-1003R; Part_type: RESISTORS\FIXED; Project: VOCERA; RoHS: RoHS; Temperature: -55°C+155°C; Tolerance: 1%; Voltage: NA; Wattage: 1/16W; Weight: 0.65mg; Datasheet: Y:\MIS_DATABASE\DATASHEETS\RESISTORS\RCXXXXL-SER_MAR18.PDF
R235 R505 R1295 = RESISTOR: RES 56.2K 1/10W 1% 0402; Chkd/date: VASANTHA/201216; Crtd /date: MAZHAR/211009; Custom_Duty: 15%; Customs_HS_Code: 85332119; Distributor_name: DIGIKEY; Distributor_part_number: P56.2KLCT-ND; Footprint Path: Y:\MIS_DATABASE\Library\ALTIUM_TOOL\PCB_FOOTPRINTS\Altium_Footprint_Lib.PcbLib; Height: 0.40MM; Library Path: Y:\MIS_DATABASE\Library\ALTIUM_TOOL\SCHEMATICS_PARTS\MS_DISCRETE_Library.schlib; Manufacturer: PANASONIC-ECG; Mfr_name: PANASONIC-ECG; Mfr_part_number: ERJ-2RKF5622X; Mistral Part No: 110009100014-R; Package: 0402; Part #: 102145-2493R; Part_type: RESISTORS\FIXED; Project: GOLDEN-I; RoHS: RoHS; Temperature: -55°C+155°C; Tolerance: 1%; Voltage: NA; Wattage: 1/10W; Weight: 0.8mg; Datasheet: Y:\MIS_DATABASE\DATASHEETS\RESISTORS\PAN-ERJSER_NOV17.PDF
R237 R521 R1297 = RESISTOR: RES 24.9K 1/16W 1% 0402; Chkd/date: MANIRAJA/121017; Crtd /date: MANIRAJA/121017; Custom_Duty: 15%; Customs_HS_Code: 85332119; Distributor_name: DIGIKEY; Distributor_part_number: 311-24.9KLRCT-ND; Footprint Path: Y:\MIS_DATABASE\Library\ALTIUM_TOOL\PCB_FOOTPRINTS\Altium_Footprint_Lib.PcbLib; Height: 0.40MM; Library Path: Y:\MIS_DATABASE\Library\ALTIUM_TOOL\SCHEMATICS_PARTS\MS_DISCRETE_Library.schlib; Manufacturer: YAGEO AMERICA; Mfr_name: YAGEO AMERICA; Mfr_part_number: RC0402FR-0724K9L; Mistral Part No: 110009030538-R; Package: 0402; Part #: 102145-5363R; Part_type: RESISTORS\FIXED; Project: P4_RADAR_DI; RoHS: RoHS; Temperature: -55°C+155°C; Tolerance: 1%; Voltage: NA; Wattage: 1/16W; Weight: 0.65mg; Datasheet: Y:\MIS_DATABASE\DATASHEETS\RESISTORS\RCXXXXL-SER_MAR18.PDF
R318 R324 R1294 R1298-R1300 = RESISTOR: RES 0E 1/10W JUMPER 0402; Chkd/date: VASANTHA/061216; Crtd /date: NAVEED/201014; Custom_Duty: 15%; Customs_HS_Code: 85332119; Distributor_name: DIGIKEY; Distributor_part_number: P0.0JCT-ND; Footprint Path: Y:\MIS_DATABASE\Library\ALTIUM_TOOL\PCB_FOOTPRINTS\Altium_Footprint_Lib.PcbLib; Height: 0.40MM; IBISSP_MODLES: VALUE REPEATING 2 TIME; Library Path: Y:\MIS_DATABASE\Library\ALTIUM_TOOL\SCHEMATICS_PARTS\MS_DISCRETE_Library.schlib; Manufacturer: PANASONIC-ECG; Mfr_name: PANASONIC-ECG; Mfr_part_number: ERJ-2GE0R00X; Mistral Part No: 110018030052-R; Package: 0402; Part_type: RESISTORS\FIXED; Project: AEGIS POM; RoHS: RoHS; Temperature: -55°C+155°C; Tolerance: NA; Voltage: NA; Wattage: 1/10W; Weight: 0.8mg; Datasheet: Y:\MIS_DATABASE\DATASHEETS\RESISTORS\PAN-ERJSER_NOV17.PDF
R406 = RESISTOR: RES 24.9K 1/16W 1% 0402; Chkd/date: MANIRAJA/121017; Crtd /date: MANIRAJA/121017; Custom_Duty: 15%; Customs_HS_Code: 85332119; Distributor_name: DIGIKEY; Distributor_part_number: 311-24.9KLRCT-ND; Footprint Path: Y:\MIS_DATABASE\Library\ALTIUM_TOOL\PCB_FOOTPRINTS\Altium_Footprint_Lib.PcbLib; Height: 0.40MM; Library Path: Y:\MIS_DATABASE\Library\ALTIUM_TOOL\SCHEMATICS_PARTS\MS_DISCRETE_Library.schlib; Manufacturer: YAGEO AMERICA; Mfr_name: YAGEO AMERICA; Mfr_part_number: RC0402FR-0724K9L; Mistral Part No: 110009030538-R; Package: 0402; Part #: 102145-2493R; Part_type: RESISTORS\FIXED; Project: P4_RADAR_DI; RoHS: RoHS; Temperature: -55°C+155°C; Tolerance: 1%; Voltage: NA; Wattage: 1/16W; Weight: 0.65mg; Datasheet: Y:\MIS_DATABASE\DATASHEETS\RESISTORS\RCXXXXL-SER_MAR18.PDF
R410 = RESISTOR: RES 53.6K 1/10W 1% 0402; Chkd/date: ALVY/020620; Crtd /date: MANIRAJA/020620; Custom_Duty: 15%; Customs_HS_Code: 85332119; Distributor_name: DIGIKEY; Distributor_part_number: 2019-RK73H1ETTP5362FCT-ND; Footprint Path: Y:\MIS_DATABASE\Library\ALTIUM_TOOL\PCB_FOOTPRINTS\Altium_Footprint_Lib.PcbLib; Height: 0.40MM; Library Path: Y:\MIS_DATABASE\Library\ALTIUM_TOOL\SCHEMATICS_PARTS\MS_DISCRETE_Library.schlib; Manufacturer: KOA SPEER; Mfr_name: KOA SPEER; Mfr_part_number: RK73H1ETTP5362F; Mistral Part No: 110020060014-R; Package: 0402; Part #: 102145-5363R; Part_type: RESISTORS\FIXED; Project: 32CHSCC CONTROLLER CARD; RoHS: RoHS; Temperature: -55°C+155°C; Tolerance: 1%; Voltage: NA; Wattage: 1/10W; Weight: 0.65mg; Datasheet: Y:\MIS_DATABASE\DATASHEETS\RESISTORS\RK73H-SER.PDF
TP52 TP137 TP173 = TESTPOINT: TESTPOINT CIR 30 SMD; Chkd/date: SHREESHAIL/171006; Crtd /date: MAZHAR/171006; Custom_Duty: NA; Customs_HS_Code: NA; Distributor_name: NA; Distributor_part_number: NA; Footprint Path: Y:\MIS_DATABASE\Library\ALTIUM_TOOL\PCB_FOOTPRINTS\Altium_Footprint_Lib.PcbLib; Height: NA; Library Path: Y:\MIS_DATABASE\Library\ALTIUM_TOOL\SCHEMATICS_PARTS\MS_DISCRETE_Library.schlib; MECHANICAL 3D STEP FILE: NA; Manufacturer: LOCAL; Mfr_name: LOCAL; Mistral Part No: 130009030930; Package: SMD; Part #: NO-POP; Project: BT MODULE_CSRBC04; RoHS: NA; Temperature: NA; Tolerance: NA; Voltage: NA; Wattage: NA; Weight: NA; Datasheet: NA
U41 U63 U66 U85 = TPS74501_WSON6: IC 500mA ADJ OUTPUT LDO WITH POWER-GOOD WSON6; Chkd/date: MANIRAJA/170122; Crtd /date: TAMILARASU/170122; Custom_Duty: 15%; Customs_HS_Code: 85423100; Distributor_name: DIGIKEY; Distributor_part_number: 296-TPS74501PQWDRVRQ1CT-ND; Footprint Path: Y:\MIS_DATABASE\Library\ALTIUM_TOOL\PCB_FOOTPRINTS\Altium_Footprint_Lib.PcbLib; Height: 0.80MM; Library Path: Y:\MIS_DATABASE\Library\ALTIUM_TOOL\SCHEMATICS_PARTS\MS_MISCPOWER_Library.schlib; Manufacturer: TEXAS INSTRUMENTS; Mfr_name: TEXAS INSTRUMENTS; Mistral Part No: 142022010008-R; Package: WSON6; Part_type: ICS\POWER\VOLTAGE REGULATOR; Project: J7AHP_PROTO_BRD; RoHS: RoHS; Temperature: -40°C+125°C; Tolerance: NA; Voltage: NA; Wattage: NA; Weight: NA; Datasheet: Y:\MIS_DATABASE\DATASHEETS\ICS\POWER\TPS74501.PDF
U53 = TLV7103318D_WSON6: IC REGULATOR LDO LINEAR 200mA WSON6; Automotive Alternate_mfr_name: TEXAS INSTRUMENTS; Automotive Alternate_mfr_part_number: TLV7103318QDSERQ1; Chkd/date: NAVEED/080415; Crtd /date: JEBRAN/300315; Custom_Duty: 15%; Customs_HS_Code: 85423100; Distributor_name: DIGIKEY; Distributor_part_number: 296-29058-1-ND; Height: 0.80MM; Manufacturer: TEXAS INSTRUMENTS; Mfr_name: TEXAS INSTRUMENTS; Mistral Part No: 142015030017-R; Package: WSON6; Part_type: ICS\POWER\VOLTAGE REGULATOR; Project: DUET BOARDS; RoHS: RoHS; Temperature: -40°C+125°C; Tolerance: NA; Voltage: NA; Wattage: NA; Weight: NA; Datasheet: Y:\MIS_DATABASE\DATASHEETS\MISC\REGULATORS\TLV71-SER.PDF
U62 U75 = TPS22965DSGT_WSON8: IC 6A,16mOHM ON RESISTANCE LOAD SWITCH WSON8; Chkd/date: MANIRAJA/110817; Crtd /date: MANIRAJA/110817; Custom_Duty: 15%; Customs_HS_Code: 85423100; Distributor_name: DIGIKEY; Distributor_part_number: 296-42375-1-ND; Height: 0.80MM; Manufacturer: TEXAS INSTRUMENTS; Mfr_name: TEXAS INSTRUMENTS; Mistral Part No: 142017080006-R; Package: WSON8; Part_type: ICS\POWER\DRIVER; Project: TI_SVB_MAXWELL_DUT; RoHS: RoHS; Temperature: -40°C+105°C; Tolerance: NA; Voltage: NA; Wattage: NA; Weight: 11mg; Datasheet: Y:\MIS_DATABASE\DATASHEETS\ICS\POWER\TPS22965N.PDF
U67 = TLV733P-Q1_WSON6: IC 1.8V 300mA CAPACITOR-FREE LDO LINEAR REGULATOR WSON6; Chkd/date: MANIRAJA/140421; Crtd /date: ALVY/140421; Custom_Duty: 15%; Customs_HS_Code: 85423100; Distributor_name: DIGIKEY; Distributor_part_number: 296-44836-1-ND; Footprint Path: Y:\MIS_DATABASE\Library\ALTIUM_TOOL\PCB_FOOTPRINTS\Altium_Footprint_Lib.PcbLib; Height: 0.80MM; Library Path: Y:\MIS_DATABASE\Library\ALTIUM_TOOL\SCHEMATICS_PARTS\MS_MISCPOWER_Library.schlib; Manufacturer: TEXAS INSTRUMENTS; Mfr_name: TEXAS INSTRUMENTS; Mistral Part No: 142021040008-R; Package: WSON6; Part_type: ICS\POWER\VOLTAGE REGULATOR; Project: TI_J7AEP_EVM_SOM; RoHS: RoHS; Temperature: -40°C+150°C; Tolerance: NA; Voltage: NA; Wattage: NA; Weight: 8.5mg; Datasheet: Y:\MIS_DATABASE\DATASHEETS\ICS\POWER\TLV733P-Q1_OCT20.PDF
U69 = MOSFET_2N7002BK: TRANSISTOR MOSFET N-CHANNEL 50V 200mA SOT-416F; Chkd/date: ALVY/220222; Crtd /date: TAMILARASU/180222; Custom_Duty: 15%; Customs_HS_Code: 85423100; Distributor_name: DIGIKEY; Distributor_part_number: RE1J002YNTCLCT-ND; Footprint Path: Y:\MIS_DATABASE\Library\ALTIUM_TOOL\PCB_FOOTPRINTS\Altium_Footprint_Lib.PcbLib; Height: 0.85MM; Library Path: Y:\MIS_DATABASE\Library\ALTIUM_TOOL\SCHEMATICS_PARTS\MS_MOSFET_Library.schlib; Manufacturer: ROHM; Mfr_name: ROHM; Mistral Part No: 130022020037-R; Package: SOT-416F; Part_type: TRANSISTOR\MOSFET; Project: TI_J7AHP_EVM_BRD; RoHS: RoHS; Temperature: -55°C+150°C; Tolerance: NA; Voltage: NA; Wattage: NA; Weight: 2.4mg; Datasheet: Y:\MIS_DATABASE\DATASHEETS\DISCRETES\TRANSISTORS_FETS\RE1J002YN.PDF
U70 = MOSFET_NX3008CBKS: TRANSISTOR MOSFET N/P CHANNEL TRENCH 30V 350/200mA SC88-6; Chkd/date: MANIRAJA/311018; Crtd /date: ALVY/311018; Custom_Duty: 15%; Customs_HS_Code: 85412900; Distributor_name: DIGIKEY; Distributor_part_number: 1727-1278-1-ND; Footprint Path: Y:\MIS_DATABASE\Library\ALTIUM_TOOL\PCB_FOOTPRINTS\Altium_Footprint_Lib.PcbLib; Height: 1.10MM; Library Path: Y:\MIS_DATABASE\Library\ALTIUM_TOOL\SCHEMATICS_PARTS\MS_MOSFET_Library.schlib; Manufacturer: NEXPERIA; Mfr_name: NEXPERIA; Mfr_part_number: NX3008CBKS,115; Mistral Part No: 130018100059-R; Package: SC88-6; Part_type: TRANSISTOR\MOSFET; Project: TI_J7ES_EVM_SOM; RoHS: RoHS; Temperature: -55°C+150°C; Tolerance: NA; Voltage: NA; Wattage: NA; Weight: 7.51mg; Datasheet: Y:\MIS_DATABASE\DATASHEETS\DISCRETES\TRANSISTORS_FETS\NX3008CBKS.PDF
U201 = TLV733P-Q1_WSON6: IC 3.3V 300mA CAPACITOR-FREE LDO LINEAR REGULATOR WSON6; Chkd/date: MANIRAJA/140421; Crtd /date: ALVY/140421; Custom_Duty: 15%; Customs_HS_Code: 85423100; Distributor_name: DIGIKEY; Distributor_part_number: 296-44839-1-ND; Footprint Path: Y:\MIS_DATABASE\Library\ALTIUM_TOOL\PCB_FOOTPRINTS\Altium_Footprint_Lib.PcbLib; Height: 0.80MM; Library Path: Y:\MIS_DATABASE\Library\ALTIUM_TOOL\SCHEMATICS_PARTS\MS_MISCPOWER_Library.schlib; Manufacturer: TEXAS INSTRUMENTS; Mfr_name: TEXAS INSTRUMENTS; Mistral Part No: 142021040009-R; Package: WSON6; Part_type: ICS\POWER\VOLTAGE REGULATOR; Project: TI_J7AEP_EVM_SOM; RoHS: RoHS; Temperature: -40°C+150°C; Tolerance: NA; Voltage: NA; Wattage: NA; Weight: 8.5mg; Datasheet: Y:\MIS_DATABASE\DATASHEETS\ICS\POWER\TLV733P-Q1_OCT20.PDF
U279 U281 = SN74LVC1G97DBVT_SOT23-6: IC CONFIGURABLE MULTIPLE-FUNCTION GATE SOT23-6; Chkd/date: NAVEED/130715; Crtd /date: VASANTHA/180314; Custom_Duty: 15%; Customs_HS_Code: 85423100; Distributor_name: DIGIKEY; Distributor_part_number: SN74LVC1G97DBVT-ND; Height: 1.45MM; Mfr_name: TEXAS INSTRUMENTS; Mistral Part No: 141015030002-R; Part_type: ICS\DIGITAL\FLIP-FLOP; Project: MEDCARDPH1; RoHS: RoHS; Temperature: -40°C+125°C; Tolerance: NA; Voltage: NA; Wattage: NA; Weight: NA; Datasheet: Y:\MIS_DATABASE\DATASHEETS\ICS\DIGITAL\GATES\SN74LVC1G97.PDF
C1241 = CAP: CAP CERAMIC 0.1uF 50V 10% X7R 0402; Automotive Alternate_mfr_name: TDK; Automotive Alternate_mfr_part_number: CGA2B3X7R1H104K050BB; Chkd/date: MANIRAJA/261020; Crtd /date: ALVY/211020; Custom_Duty: 15%; Customs_HS_Code: 85322990; Direct Alternate_mfr_name: TDK; Direct Alternate_mfr_part_number: C1005X7R1H104K050BE; Distributor_name: DIGIKEY; Distributor_part_number: 490-10700-1-ND; Footprint Path: Y:\MIS_DATABASE\Library\ALTIUM_TOOL\PCB_FOOTPRINTS\Altium_Footprint_Lib.PcbLib; Height: 0.55MM; Library Path: Y:\MIS_DATABASE\Library\ALTIUM_TOOL\SCHEMATICS_PARTS\MS_DISCRETE_Library.schlib; Manufacturer: MURATA; Mfr_name: MURATA; Mfr_part_number: GRM155R71H104KE14D; Mistral Part No: 120011100014-R; Package: 0402; Part_type: CAPACITORS\CERAMIC; Project: J7_CP; RoHS: RoHS; Temperature: -55°C+125°C; Tolerance: 10%; Voltage: 50V; Wattage: NA; Weight: 3.1mg; Datasheet: Y:\MIS_DATABASE\DATASHEETS\CAPACITORS\GRM155R71H104KE14.PDF
J30 = HEADER_5X1: CON HDR 1X5 2.54MM PITCH ST TH; Chkd/date: MANIRAJA/190118; Crtd /date: ALVY/190118; Custom_Duty: 24%; Customs_HS_Code: 85369090; Distributor_name: DIGIKEY; Distributor_part_number: 609-4303-ND; Height: 8.58MM; Manufacturer: AMPHENOL; Mfr_name: AMPHENOL; Mfr_part_number: 68002-205HLF; Mistral Part No: 150018010010-R; Package: THRU HOLE; Part_type: CONNECTOR\HEADERS; Project: TI_SVB_MAXWELL_DUT; RoHS: RoHS; Temperature: NA; Tolerance: NA; Voltage: NA; Wattage: NA; Weight: NA; Datasheet: Y:\MIS_DATABASE\DATASHEETS\CONNECTORS\68002.PDF
Q2 = MOSFET_BSS138W: IC MOSFET N-CHANNEL 60V, SOT323; Chkd/date: SUHAS/191010; Crtd /date: MAZHAR/240907; Custom_Duty: 15%; Customs_HS_Code: 85423100; Height: 1.00MM; Manufacturer: INFINEON TECHNOLOGIES; Mfr_name: INFINEON TECHNOLOGIES; Mistral Part No: 142009030152-R; Package: SOT323; Part_type: ICS\POWER\MOSFET; Project: SMART VIEW_NVR; RoHS: RoHS; Temperature: -55°C+150°C; Voltage: 60V; Datasheet: Y:\MIS_DATABASE\DATASHEETS\DISCRETES\TRANSISTORS_FETS\BSS138W.PDF
R590 = RESISTOR: RES 10K 1/16W 5% 0402; Chkd/date: VASANTHA/061216; Crtd /date: MAZHAR/230805; Custom_Duty: 15%; Customs_HS_Code: 85332119; Distributor_name: DIGIKEY; Distributor_part_number: 311-10KJRCT-ND; Footprint Path: Y:\MIS_DATABASE\Library\ALTIUM_TOOL\PCB_FOOTPRINTS\Altium_Footprint_Lib.PcbLib; Height: 0.40MM; Library Path: Y:\MIS_DATABASE\Library\ALTIUM_TOOL\SCHEMATICS_PARTS\MS_DISCRETE_Library.schlib; Manufacturer: YAGEO AMERICA; Mfr_name: YAGEO AMERICA; Mfr_part_number: RC0402JR-0710KL; Mistral Part No: 110011060021-R; Package: 0402; Part_type: RESISTORS\FIXED; Project: HSE; RoHS: RoHS; Temperature: -55°C+155°C; Tolerance: 5%; Voltage: NA; Wattage: 1/16W; Weight: 0.65mg; Datasheet: Y:\MIS_DATABASE\DATASHEETS\RESISTORS\RCXXXXL-SER_MAR18.PDF
U269 = SN74CBTLV3125PWR_TSSOP14: IC 2.5/3.3V QUADRUPLE HIGH-BANDWIDTH FET BUS SWITCH TSSOP14; Chkd/date: MANIRAJA/241018; Crtd /date: ALVY/241018; Custom_Duty: 15%; Customs_HS_Code: 85423100; Distributor_name: DIGIKEY; Distributor_part_number: 296-16804-1-ND; Footprint Path: Y:\MIS_DATABASE\Library\ALTIUM_TOOL\PCB_FOOTPRINTS\Altium_Footprint_Lib.PcbLib; Height: 1.20MM; Library Path: Y:\MIS_DATABASE\Library\ALTIUM_TOOL\SCHEMATICS_PARTS\MS_COMBINATIONAL_Library.schlib; Manufacturer: TEXAS INSTRUMENTS; Mfr_name: TEXAS INSTRUMENTS; Mistral Part No: 141018100021-R; Package: TSSOP14; Part_type: ICS\DIGITAL\COMBINATIONAL; Project: TI_J7ES_EVM_CP; RoHS: RoHS; Temperature: -40°C+85°C; Tolerance: NA; Voltage: NA; Wattage: NA; Weight: 57.2mg; Datasheet: Y:\MIS_DATABASE\DATASHEETS\ICS\DIGITAL\COMBINATIONAL\SN74CB3Q3125.PDF
U274 = TPD4E004_SON6_0: IC 4-CH ESD PROTECTION ARRAY FOR HIGH SPEED DATA INTERFACE SON6; Chkd/date: MANIRAJA/100320; Crtd /date: MUDDU/010310; Custom_Duty: 15%; Customs_HS_Code: 85423100; Distributor_name: DIGIKEY; Distributor_part_number: 296-23618-1-ND; Footprint Path: Y:\MIS_DATABASE\Library\ALTIUM_TOOL\PCB_FOOTPRINTS\Altium_Footprint_Lib.PcbLib; Height: 0.60MM; Library Path: Y:\MIS_DATABASE\Library\ALTIUM_TOOL\SCHEMATICS_PARTS\MS_MISCINTERFACE_Library.schlib; Library Ref: TPD4E004_SON6; Mfr_name: TEXAS INSTRUMENTS; Mistral Part No: 141010020012-R; Package: SON6; Part_type: ICS\INTERFACE; Project: BUG_BASE-II; RoHS: RoHS; Temperature: -40°C+85°C; Tolerance: NA; Voltage: NA; Wattage: NA; Weight: 3.2mg; Datasheet: Y:\MIS_DATABASE\DATASHEETS\ICS\INTERFACE\TPD4E004-SER.PDF

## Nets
DGND: C171.2 C175.2 C176.2 C185.2 C198.1 C200.2 C218.2 C226.1 C236.2 C245.2 C246.2 C247.2 C255.2 C256.2 C258.2 C264.2 C265.2 C266.2 C276.2 C282.2 C283.2 C284.2 C291.2 C292.2 C296.2 C297.2 C319.2 C320.2 C718.2 C719.2 C1241.2 C1269.2 C1271.2 FL22.2 FL22.4 FL23.2 FL23.4 FL24.2 FL24.4 FL25.2 FL25.4 FL32.2 FL32.4 FL33.2 FL33.4 FL34.2 FL34.4 FL35.2 FL35.4 J30.3 Q2.2(S) Q3.1(S1) Q4.1(S1) R216.2 R228.2 R237.1 R247.1 R262.2 R265.2 R337.1 R342.1 R401.1 R407.2 R409.1 R410.1 R437.1 R521.1 R534.2 R932.2 R1297.1 U41.3(GND) U41.7(EP) U42.2(GOSNS) U42.6(GND) U42.8(GND) U42.17(EP) U48.2(GOSNS) U48.6(GND) U48.8(GND) U48.12(SDA) U48.13(SCL) U48.15(VSEL) U48.17(EP) U53.4(GND) U62.5(GND) U62.9(EP) U63.3(GND) U63.7(EP) U66.3(GND) U66.7(EP) U67.3(GND) U67.7(GND) U69.2(S) U70.1(S1) U75.5(GND) U75.9(EP) U85.3(GND) U85.7(EP) U201.3(GND) U201.7(GND) U269.7(GND) U274.3(GND) U279.2(GND) U281.1(IN1) U281.2(GND) ; also on sheet 11 12 13 14 15 16 17 18 20 21 22 23 24 25 26 27 28 29 30 31 32 33 34 35 36 37 38 39 40 41 42 43 44 45 46 47 48 49 50 51 52 53 54 55 56 57 58 59 60 61 62 63 64 65 66 67 68 69 70 76 77 78 79 81 82 83 84
VCCA_3V3: C176.1 C264.1 C265.1 C266.1 C282.1 C284.1 C291.1 C296.1 C320.1 C1269.1 Q3.4(S2) R220.1 R417.1 R1309.1 R1310.1 U41.6(IN) U62.1(VIN1) U62.2(VIN2) U62.4(VBIAS) U63.6(IN) U66.6(IN) U67.6(IN) U70.4(S2) U75.1(VIN1) U75.2(VIN2) U75.4(VBIAS) U85.6(IN) U279.5(VCC) ; also on sheet 23 54 69 70 75 81
VCCA_3V3_CORE: FL22.1 FL22.3 FL23.1 FL23.3 FL24.1 FL24.3 FL25.1 FL25.3 FL32.1 FL32.3 FL33.1 FL33.3 FL34.1 FL34.3 FL35.1 FL35.3 R223.1 R234.1 R269.1 U42.5(VIN1) U42.9(VIN2) U42.11(MODE/SYNC) U48.5(VIN1) U48.9(VIN2) ; also on sheet 75
VDD1_DDR_1V8_PG: R511.1 R1300.2 TP173.1(TP) U85.5(PG)
VDD1_DDR_1V8_REG: C319.1 C334.1 R505.2 R511.2 U85.1(OUT) ; also on sheet 75
VDD_CORE_0V8: C175.1 C200.1 C218.1 C236.1 L27.2 L28.2 U42.3(VOSNS) U48.3(VOSNS) ; also on sheet 26 27 28 54 74
VDD_CORE_HCPS_SW1: L27.1 U42.7(SW)
VDD_CORE_HCPS_SW2: L28.1 U48.7(SW)
VDD_GPIORET_IO_3V3_LS: C292.1 U75.7(VOUT1) U75.8(VOUT2) ; also on sheet 74 75
VDD_GPIORET_WK_0V8_PG: R413.1 R1299.2 TP137.1(TP) U66.5(PG)
VDD_GPIORET_WK_0V8_REG: C274.1 C283.1 R406.2 R413.2 U66.1(OUT) ; also on sheet 74
VDD_IO_1V8: Q3.2(G1) U41.4(EN) U63.4(EN) ; also on sheet 26 69 74
VDD_IO_3V3: C1271.1 R316.2 U281.5(VCC) ; also on sheet 26 54 74
VDD_IO_3V3_LS: C258.1 U62.7(VOUT1) U62.8(VOUT2) ; also on sheet 74 75
VDD_MCU_0V85: U69.1(G) ; also on sheet 26 27 28 54 69 74
VDD_MCUIO_3V3: U279.1(IN1) ; also on sheet 26 54 74
VDD_SD_DV_1V8: R324.1 U53.5(OUT2)
VDD_SD_DV_3V3: R318.1 U53.6(OUT1)
VDD_SD_DV_REG: C247.1 R318.2 R324.2 R342.2 TP98.1(TP) ; also on sheet 74
CON_PM1_SCL: J30.1 U269.3(1B) U274.1(IO1)
CON_PM1_SDA: J30.2 U269.6(2B) U274.2(IO2)
CON_PM2_SCL: J30.5 U269.11(4B) U274.5(IO4)
CON_PM2_SDA: J30.4 U269.8(3B) U274.4(IO3)
EN_3V3_VIO: R337.2 R401.2 R932.1 U53.3(EN2) U62.3(ON) U201.4(EN) U281.3(IN0) ; also on sheet 54 65 69
EN_DDR_RET_1V1: Q4.2(G1) ; also on sheet 14 69
EN_DDR_VDD1: Q3.3(D2) R534.1 U85.4(EN)
EN_EFUSE_VPP: R407.1 U67.4(EN) ; also on sheet 18
EN_GPIO_RET_3V3: U70.2(G1) U279.6(IN2) ; also on sheet 69
EN_GPIORET_VIO: R437.2 U75.3(ON) U279.4(Y)
EN_GPIORET_WKLG: R409.2 U66.4(EN) U70.3(D2)
EN_SD_3V3: U53.1(EN1) U281.4(Y)
H_WKUP_I2C0_SCL: U42.13(SCL) ; also on sheet 23 54 69 70
H_WKUP_I2C0_SDA: U42.12(SDA) ; also on sheet 23 54 69 70
HCPS_B_CORE_FSEL_PH1: R228.1 R234.2 U42.16(FSEL)
HCPS_B_CORE_FSEL_PH2: R265.1 R269.2 U48.16(FSEL)
HCPS_B_CORE_PG: C171.1 R213.2 TP51.1(TP)
HCPS_B_CORE_VSEL: R216.1 R223.2 U42.15(VSEL)
HCPS_B_SY_OUT_PH2: R262.1 U48.14(SYNC_OUT)
HCPS_B_SYNC_OUT_PH1: U42.14(SYNC_OUT) U48.11(MODE/SYNC)
MAIN_PWRGRP_IRQn: R1294.1 R1298.1 R1300.1 U42.4(EN) U48.4(EN) ; also on sheet 54 69 70
MCU_PWRGRP_IRQn: R1299.1 ; also on sheet 54 69
PM1_SCL: U269.2(1A) ; also on sheet 47 63 76 78
PM1_SDA: U269.5(2A) ; also on sheet 47 63 76 78
PM2_SCL: U269.12(4A) ; also on sheet 47 62 63 77 79
PM2_SDA: U269.9(3A) ; also on sheet 47 62 63 77 79
PM_OE#: Q2.3(D) R590.2 U269.1(~{1OE}) U269.4(~{2OE}) U269.10(~{3OE}) U269.13(~{4OE})
SEL_SDIO_3V3_1V8n: R316.1 U281.6(IN2) ; also on sheet 20
SYS_PWR_PG: Q2.1(G) ; also on sheet 35 36
VDA_PHY_1V8_PG: R209.1 R1298.2 TP52.1(TP) U41.5(PG)
VDA_PHY_1V8_REG: C185.1 C192.1 R209.2 R235.2 U41.1(OUT) ; also on sheet 74
VDA_PLL_1V8_PG: R1294.2 R1296.1 U63.5(PG)
VDA_PLL_1V8_REG: C256.1 R1295.2 R1296.2 U63.1(OUT) ; also on sheet 74
VDA_USB_3V3_REG: C718.1 U201.1(OUT) ; also on sheet 74
VPP_EFUSE_1V8: C276.1 U67.1(OUT) ; also on sheet 22
VSYS_3V3: C1241.1 R590.1 U269.14(VCC) ; also on sheet 22 23 35 36 40 47 49 62 63 65 66 67 68 69 75 76 77 78 79
VSYS_5V0: C245.1 C246.1 C719.1 U53.2(IN) U201.6(IN) ; also on sheet 20 30 31 50 52 59 65 68 81 82 83 84
N35600802: C189.2 C198.2 C226.2 U42.1(COMP) U48.1(COMP)
N35600892: R213.1 R220.2 U42.10(PG) U48.10(PG)
N35601446: C189.1 R247.2
N35603723: R417.2 U69.3(D) U70.5(G2) U70.6(D1)
N35603798: C274.2 R406.1 R410.2 U66.2(FB)
N35603915: C192.2 R235.1 R237.2 U41.2(FB)
N35604551: C297.1 U75.6(CT)
N35604832: C255.1 U62.6(CT)
N35605554: C334.2 R505.1 R521.2 U85.2(FB)
N39039668: R1295.1 R1297.2 U63.2(FB)
N40559760: R1309.2 U279.3(IN0)
N41254916: Q3.5(G2) Q3.6(D1) Q4.6(D1) R1310.2

Not connected (* = marked no-connect by the designer): U67 2(NC1)* 5(NC2)*; U201 2(NC1)* 5(NC2)*; U274 6(VCC)*

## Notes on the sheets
sheet 71
- VDD_CORE_0V8 High-Current Power Stage A (HCPS-B)
- FB_VDD_CORE_0V8_P
- FB_VDD_CORE_0V8_N
- Pulled-Up to VCCA_3V3 at PMIC
- Route remote sense as "VDD_xxx_P / _N"
  as pseudo differential pair trace.
- VSEL=> 0.8V Boot & 0x43 I2C ADDR
- FSEL = 2.25MHz
- (See "PCB Notes")
- Line to Shape keepout needs to be given in layout
  for VDD_CORE and DGND feedback traces
- Note: Via keepout areas need to be applied to positive &
  negative remote sense traces/nets
  (i.e. “VDD_xxx_HCPS_VOSNS/_GOSNS”)
  both at the buck & along diff trace routing path between
  buck”xOSNS” pins to ensure no unwanted power
  or Gnd connections are made before reaching the
  desired remote sense location where only 1x power
  & Gnd connection should be made
- FB_VDD_CORE_0V8_P
- FB_VDD_CORE_0V8_N
- FSEL = 2.25MHz
sheet 72
- LOAD SWITCHES
- VDD_GPIORET_IO_3V3
- VDD_IO_3V3
- OR GATE
- VDA_PLL_1V8
- LDOs
- VDD_GPIORET_WK_0V8
- VDA_PHY_1V8
- VDA_USB_3V3
- VDD1_DDR_1V8
- EN_GPIORET_VIO & EN_GPIORET_WKLG &  EN_DDR_VDD1 Truth table
- "OR" Gate Logic
- States
- X
- Y
- OUTPUT
- Input - X
- Output
- Input - Y
- 0
- 0
- 0
- OFF
- OFF
- OFF
- 0
- 1
- 1
- OFF
- ON
- ON
- 1
- 0
- 1
- ON
- OFF
- ON
- 1
- 1
- 1
- ON
- ON
- ON
- VDD_SD_DV
- VPP_EFUSE_1V8
- AND GATE
- Source from SoC GPIO
- Note: Resistor is to 'bleed' off voltage.
sheet 73
- EVM POWER MEASUREMENT I2C BUS ISOLATION
- EVM development & evaluation Test circuitry
- (TI EVM Only)
- Silkscreen:"EXT_PM"
- Place near connector J30
